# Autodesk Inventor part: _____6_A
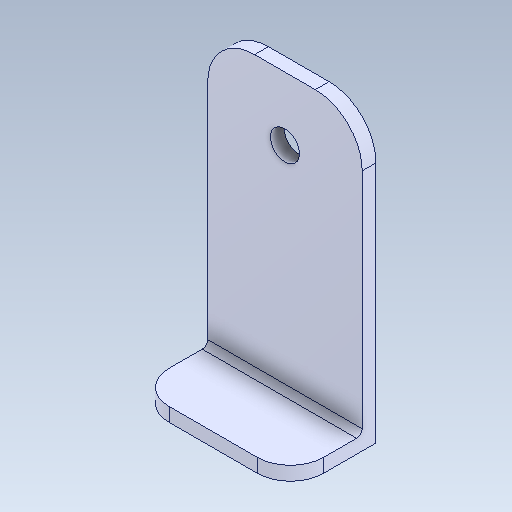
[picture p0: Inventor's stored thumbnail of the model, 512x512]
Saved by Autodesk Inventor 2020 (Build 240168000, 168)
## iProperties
Created: 2017-09
Part Number: _____6_A
Material: Générique
Document SubType Name: Modeling
Designer: bruno
Density: 1 g/cm^3
Appearance: Par défaut
Author: bruno
Sending System: SolidWorks 2016
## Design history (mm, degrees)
feature "Importée1"
node "Solide1"
